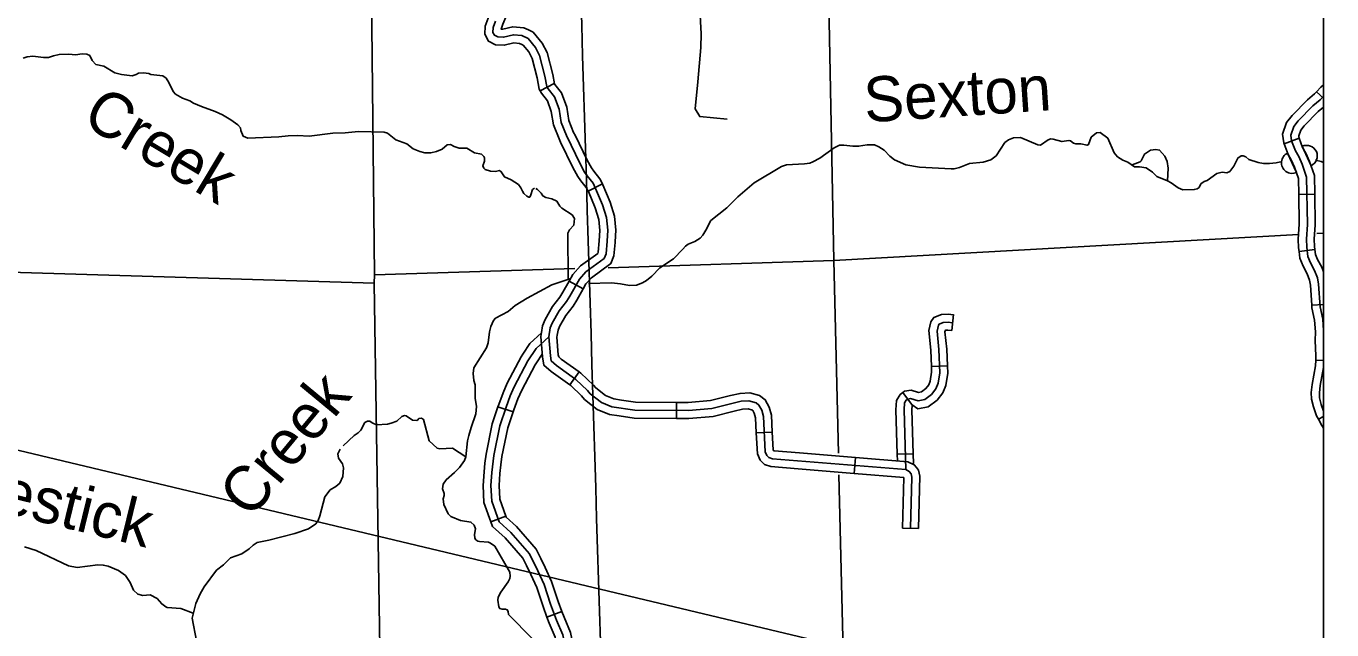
# Model space of a CAD drawing. Extents: x 1212896 to 1368412, y 378476 to 478763.
# Drawn here: x 1307154 to 1319396, y 397540 to 403202 of the extents above; entities that cross this region are included whole.
import ezdxf

# ---------------------------------------------------------------- set-up
doc = ezdxf.new("R2010")
doc.units = 0
for name, color, linetype in [('1', 7, 'Continuous'), ('Level 31', 7, 'Continuous'), ('Level 32', 7, 'Continuous'), ('Level 35', 7, 'Continuous'), ('Level 38', 7, 'Continuous'), ('Level 4', 7, 'Continuous'), ('Level 45', 7, 'Continuous'), ('Level 5', 7, 'Continuous'), ('Level 60', 7, 'Continuous'), ('R_Draft', 7, 'Continuous')]:
    doc.layers.add(name, color=color, linetype=linetype)

msp = doc.modelspace()

# ---------------------------------------------------------------- linework, layer by layer
at = {"layer": '1'}
msp.add_lwpolyline([(1257400, 437504), (1319317, 437504), (1319317, 388319), (1257400, 388319)], close=True, dxfattribs=at)
at = {"layer": 'Level 31'}
for p, q in [((1312105, 402665), (1311973, 402595)), ((1312423, 401654), (1312557, 401722)), ((1312245, 400812), (1312376, 400739)), ((1312133, 400305), (1312133, 400305)), ((1312338, 399961), (1312251, 399839)), ((1313252, 399524), (1313253, 399674)), ((1314149, 399395), (1313999, 399387)), ((1314918, 399007), (1314930, 399157)), ((1315519, 398491), (1315369, 398495))]:
    msp.add_line(p, q, dxfattribs=at)
for points in [[(1311801, 403030), (1311779, 403040), (1311727, 403046), (1311637, 403023), (1311555, 403028), (1311490, 403060), (1311455, 403126), (1311458, 403203), (1311485, 403278), (1311522, 403362)], [(1312415, 401798), (1312390, 401832), (1312347, 401911), (1312219, 402175), (1312171, 402297), (1312151, 402422), (1312107, 402540), (1312048, 402614), (1312035, 402637), (1312017, 402734), (1311968, 402927), (1311929, 403001), (1311860, 403085), (1311800, 403113), (1311722, 403121), (1311630, 403098), (1311575, 403102), (1311545, 403117), (1311531, 403143), (1311532, 403189), (1311554, 403250)], [(1311864, 403166), (1311820, 403186), (1311717, 403197), (1311622, 403174), (1311607, 403175), (1311624, 403222), (1311659, 403301)], [(1312107, 402662), (1312091, 402750), (1312038, 402954), (1311992, 403043), (1311907, 403146), (1311864, 403166)], [(1311973, 402595), (1311964, 402612), (1311944, 402718), (1311897, 402900), (1311866, 402960), (1311813, 403024), (1311801, 403030)], [(1312300, 402180), (1312287, 402205), (1312243, 402316), (1312224, 402441), (1312173, 402578), (1312110, 402656), (1312105, 402665)], [(1311973, 402595), (1311985, 402572), (1312041, 402503), (1312078, 402403), (1312098, 402277), (1312150, 402145), (1312165, 402114)], [(1312557, 401722), (1312533, 401769), (1312475, 401843), (1312454, 401872), (1312414, 401946), (1312300, 402180)], [(1312165, 402114), (1312280, 401877), (1312327, 401792), (1312356, 401752), (1312406, 401688), (1312423, 401654)], [(1312574, 401023), (1312592, 401067), (1312603, 401185), (1312608, 401288), (1312596, 401406), (1312559, 401525), (1312493, 401681), (1312469, 401729), (1312415, 401798)], [(1312528, 401188), (1312528, 401190), (1312533, 401286), (1312522, 401390), (1312488, 401499), (1312425, 401650), (1312423, 401654)], [(1312677, 401174), (1312678, 401179), (1312684, 401290), (1312669, 401421), (1312629, 401550), (1312561, 401713), (1312557, 401722)], [(1312245, 400812), (1312279, 400873), (1312353, 400955), (1312513, 401071), (1312518, 401084), (1312528, 401188)], [(1312376, 400739), (1312402, 400785), (1312454, 400843), (1312636, 400975), (1312665, 401049), (1312677, 401174)], [(1312069, 400111), (1312054, 400288), (1312068, 400372), (1312086, 400418), (1312153, 400531), (1312220, 400620), (1312252, 400670), (1312341, 400829), (1312403, 400899), (1312574, 401023)], [(1311985, 400329), (1311995, 400392), (1312019, 400451), (1312090, 400572), (1312158, 400662), (1312187, 400708), (1312245, 400812)], [(1312376, 400739), (1312316, 400632), (1312282, 400577), (1312215, 400489), (1312154, 400385), (1312141, 400352), (1312133, 400305)], [(1312251, 399839), (1312078, 399962), (1312009, 400022), (1311994, 400101), (1311979, 400291), (1311985, 400329)], [(1312133, 400305), (1312130, 400285), (1312143, 400121), (1312147, 400101), (1312171, 400079), (1312338, 399961)], [(1312441, 399755), (1312418, 399785), (1312308, 399890), (1312125, 400020), (1312078, 400062), (1312069, 400111)], [(1312737, 399696), (1312664, 399706), (1312585, 399739), (1312494, 399809), (1312473, 399835), (1312356, 399948), (1312338, 399961)], [(1312715, 399547), (1312624, 399560), (1312509, 399608), (1312388, 399702), (1312362, 399734), (1312260, 399832), (1312251, 399839)], [(1315444, 398493), (1315459, 398974), (1315452, 399004), (1315433, 399027), (1315400, 399043), (1314152, 399146), (1314117, 399158), (1314099, 399176), (1314084, 399210), (1314067, 399541), (1314051, 399600), (1314024, 399648), (1313997, 399669), (1313931, 399687), (1313858, 399684), (1313582, 399618), (1313364, 399598), (1312861, 399602), (1312644, 399633), (1312547, 399673), (1312441, 399755)], [(1313253, 399674), (1312866, 399677), (1312737, 399696)], [(1313253, 399674), (1313361, 399673), (1313569, 399692), (1313757, 399737)], [(1313757, 399737), (1313848, 399758), (1313940, 399763), (1314031, 399738), (1314083, 399698), (1314121, 399628), (1314141, 399553), (1314149, 399395)], [(1313792, 399591), (1313594, 399543), (1313367, 399523), (1313252, 399524)], [(1313999, 399387), (1313992, 399529), (1313981, 399572), (1313966, 399598), (1313963, 399601), (1313923, 399612), (1313869, 399609), (1313792, 399591)], [(1313252, 399524), (1312855, 399527), (1312715, 399547)], [(1314392, 399051), (1314136, 399072), (1314076, 399092), (1314036, 399133), (1314010, 399192), (1313999, 399387)], [(1314404, 399200), (1314167, 399220), (1314160, 399222), (1314158, 399228), (1314149, 399395)], [(1314930, 399157), (1314404, 399200)], [(1314930, 399157), (1315420, 399116), (1315481, 399087), (1315500, 399063)], [(1314918, 399007), (1314392, 399051)], [(1315384, 398969), (1314918, 399007)], [(1315369, 398495), (1315384, 398969)], [(1315500, 399063), (1315521, 399037), (1315534, 398981), (1315519, 398491)]]:
    msp.add_lwpolyline(points, dxfattribs=at)
at = {"layer": 'Level 32'}
for p, q in [((1319317, 402527), (1319252, 402587)), ((1319088, 402150), (1318948, 402098)), ((1319236, 401626), (1319086, 401624)), ((1319237, 401107), (1319088, 401088)), ((1319317, 400593), (1319207, 400586)), ((1315834, 400347), (1315849, 400497)), ((1319317, 400066), (1319244, 400069)), ((1315791, 400016), (1315641, 400010)), ((1315463, 399646), (1315372, 399766)), ((1319317, 399541), (1319270, 399515)), ((1315470, 399190), (1315320, 399187))]:
    msp.add_line(p, q, dxfattribs=at)
for points in [[(1311554, 403250), (1311532, 403189), (1311531, 403143), (1311545, 403117), (1311575, 403102), (1311630, 403098), (1311722, 403121), (1311800, 403113), (1311860, 403085), (1311929, 403001), (1311968, 402927), (1312017, 402734), (1312035, 402637), (1312048, 402614), (1312107, 402540), (1312151, 402422), (1312171, 402297), (1312219, 402175), (1312347, 401911), (1312390, 401832), (1312415, 401798)], [(1319317, 402651), (1319291, 402630), (1319252, 402587)], [(1319252, 402587), (1319232, 402566), (1319166, 402511), (1319022, 402365), (1318969, 402298), (1318933, 402188), (1318944, 402109), (1318948, 402098)], [(1319317, 402546), (1319285, 402511), (1319217, 402455), (1319079, 402315), (1319038, 402262), (1319011, 402180), (1319018, 402127), (1319054, 402032), (1319085, 401978), (1319116, 401907), (1319159, 401786), (1319167, 401342)], [(1319317, 402442), (1319267, 402400), (1319135, 402266), (1319104, 402226), (1319086, 402173), (1319090, 402145)], [(1319088, 402150), (1319121, 402063), (1319151, 402011), (1319185, 401934), (1319233, 401800), (1319236, 401626)], [(1318948, 402098), (1318985, 401999), (1319017, 401943), (1319045, 401879), (1319083, 401772), (1319086, 401624)], [(1312415, 401798), (1312469, 401729), (1312493, 401681), (1312559, 401525), (1312596, 401406), (1312608, 401288), (1312603, 401185), (1312592, 401067), (1312574, 401023)], [(1319086, 401624), (1319090, 401344), (1319080, 401205), (1319084, 401123), (1319088, 401088)], [(1319236, 401626), (1319240, 401340), (1319231, 401203), (1319233, 401135), (1319237, 401107)], [(1319167, 401342), (1319157, 401204), (1319160, 401129), (1319171, 401043), (1319195, 400982), (1319234, 400910), (1319261, 400842), (1319271, 400781), (1319285, 400571), (1319310, 400454), (1319317, 400349)], [(1319088, 401088), (1319096, 401025), (1319125, 400950), (1319164, 400878), (1319187, 400821), (1319195, 400772), (1319207, 400586)], [(1319237, 401107), (1319243, 401062), (1319261, 401013), (1319301, 400941), (1319317, 400899)], [(1312574, 401023), (1312403, 400899), (1312341, 400829), (1312252, 400670), (1312220, 400620), (1312153, 400531), (1312086, 400418), (1312068, 400372), (1312054, 400288), (1312069, 400111)], [(1319207, 400586), (1319209, 400560), (1319234, 400444), (1319242, 400336), (1319239, 400253), (1319246, 400110), (1319244, 400069)], [(1315840, 400421), (1315797, 400425), (1315752, 400423), (1315715, 400408), (1315708, 400397), (1315694, 400341), (1315711, 400169), (1315720, 399952), (1315705, 399853), (1315682, 399800), (1315643, 399749), (1315580, 399702), (1315516, 399689), (1315445, 399709), (1315419, 399705), (1315405, 399695), (1315389, 399669), (1315386, 399604), (1315400, 399043)], [(1315849, 400496), (1315799, 400502), (1315736, 400498), (1315664, 400470), (1315637, 400429), (1315617, 400347), (1315635, 400164), (1315641, 400010)], [(1315832, 400347), (1315795, 400351), (1315772, 400350), (1315768, 400335), (1315785, 400174), (1315791, 400016)], [(1319317, 400307), (1319316, 400254), (1319317, 400219)], [(1312069, 400111), (1312078, 400062), (1312125, 400020), (1312308, 399890), (1312418, 399785), (1312441, 399755)], [(1319244, 400069), (1319242, 400016), (1319211, 399843), (1319202, 399765), (1319204, 399704), (1319223, 399631), (1319252, 399548), (1319270, 399515)], [(1315641, 400010), (1315643, 399956), (1315631, 399874), (1315616, 399839), (1315589, 399804), (1315548, 399773), (1315519, 399768), (1315451, 399787), (1315388, 399778), (1315372, 399766)], [(1315791, 400016), (1315794, 399948), (1315776, 399833), (1315747, 399763), (1315695, 399696), (1315610, 399633), (1315513, 399613), (1315460, 399651)], [(1319317, 400002), (1319287, 399832), (1319279, 399762), (1319280, 399715), (1319296, 399653), (1319317, 399593)], [(1312441, 399755), (1312547, 399673), (1312644, 399633), (1312861, 399602), (1313364, 399598), (1313582, 399618), (1313858, 399684), (1313931, 399687), (1313997, 399669), (1314024, 399648), (1314051, 399600), (1314067, 399541), (1314084, 399210), (1314099, 399176), (1314117, 399158), (1314152, 399146), (1315400, 399043), (1315433, 399027), (1315452, 399004), (1315459, 398974), (1315444, 398493)], [(1315372, 399766), (1315348, 399747), (1315313, 399693), (1315309, 399605), (1315320, 399187)], [(1315463, 399646), (1315461, 399645), (1315459, 399603), (1315470, 399190)], [(1319270, 399515), (1319301, 399456), (1319317, 399433)], [(1315320, 399187), (1315322, 399126)], [(1315470, 399190), (1315472, 399101)]]:
    msp.add_lwpolyline(points, dxfattribs=at)
at = {"layer": 'Level 35'}
for points in [[(1307127, 402901), (1307163, 402913), (1307218, 402919), (1307317, 402907), (1307365, 402907), (1307411, 402925), (1307465, 402937), (1307554, 402939), (1307617, 402932), (1307680, 402941), (1307722, 402938), (1307750, 402928), (1307774, 402881), (1307807, 402842)], [(1307807, 402842), (1307884, 402827), (1307985, 402764), (1308049, 402750), (1308147, 402736), (1308185, 402748), (1308207, 402762), (1308256, 402763), (1308304, 402757), (1308322, 402749), (1308437, 402735), (1308468, 402713), (1308493, 402672), (1308532, 402588), (1308555, 402564), (1308620, 402528), (1308688, 402501), (1308723, 402481), (1308798, 402449), (1308925, 402403), (1308996, 402369), (1309072, 402322), (1309139, 402278), (1309163, 402248), (1309168, 402223), (1309189, 402170), (1309232, 402151), (1309523, 402163), (1309611, 402172), (1309698, 402175), (1309809, 402171), (1310030, 402198), (1310146, 402200), (1310270, 402213), (1310512, 402207), (1310541, 402198), (1310619, 402136), (1310724, 402097), (1310782, 402051), (1310844, 402027), (1310893, 402014), (1310949, 402014), (1311000, 402027), (1311054, 402049), (1311100, 402088), (1311132, 402092), (1311167, 402072), (1311214, 402058), (1311285, 402059), (1311359, 402015), (1311422, 402001), (1311444, 401979), (1311450, 401966), (1311450, 401936), (1311437, 401892), (1311444, 401870), (1311458, 401859), (1311508, 401841), (1311556, 401839), (1311591, 401847), (1311609, 401837), (1311638, 401790), (1311702, 401762), (1311771, 401716), (1311793, 401687), (1311809, 401656)], [(1313222, 401020), (1313312, 401110), (1313336, 401140), (1313362, 401159), (1313423, 401183), (1313472, 401213), (1313499, 401242), (1313528, 401290), (1313573, 401378), (1313723, 401498), (1313828, 401601), (1313979, 401733), (1314236, 401886), (1314282, 401901), (1314450, 401910), (1314500, 401917), (1314531, 401929), (1314596, 401965), (1314730, 402062), (1314778, 402085), (1314820, 402087), (1314903, 402075), (1314959, 402075), (1315039, 402090), (1315108, 402089), (1315149, 402071), (1315198, 402040), (1315250, 401982), (1315295, 401949), (1315402, 401900), (1315529, 401879), (1315826, 401864), (1315856, 401865), (1315905, 401877), (1315999, 401915), (1316125, 401926), (1316197, 401948), (1316247, 401985), (1316329, 402110), (1316363, 402137), (1316411, 402155), (1316476, 402157), (1316638, 402088), (1316664, 402085), (1316736, 402136), (1316762, 402144), (1316784, 402142), (1316865, 402119), (1316930, 402130), (1316946, 402127), (1316973, 402106), (1316994, 402099), (1317042, 402098), (1317101, 402085), (1317115, 402091), (1317138, 402160)], [(1317138, 402160), (1317188, 402203), (1317224, 402205), (1317295, 402151), (1317356, 402014), (1317386, 401975), (1317435, 401944), (1317483, 401926), (1317545, 401883), (1317591, 401883), (1317656, 401873), (1317714, 401832), (1317756, 401792), (1317855, 401752), (1317888, 401733), (1317955, 401685), (1317998, 401667), (1318105, 401670), (1318133, 401676), (1318151, 401689), (1318167, 401722), (1318199, 401745), (1318227, 401755), (1318318, 401821), (1318367, 401832), (1318410, 401827), (1318438, 401838), (1318476, 401889), (1318514, 401964), (1318545, 401985), (1318565, 401986), (1318590, 401976), (1318618, 401952), (1318705, 401924), (1318753, 401914), (1318811, 401913), (1318872, 401920), (1318913, 401928)], [(1317522, 401901), (1317599, 401930), (1317609, 401940), (1317639, 402002), (1317696, 402038), (1317745, 402046), (1317780, 402039), (1317829, 401984), (1317850, 401933), (1317860, 401871), (1317855, 401752)], [(1319243, 401946), (1319295, 401934), (1319317, 401924)], [(1311809, 401656), (1311820, 401633), (1311848, 401607), (1311868, 401597), (1311875, 401598), (1311887, 401619), (1311903, 401669), (1311920, 401682)], [(1311932, 401678), (1311947, 401670), (1311983, 401636), (1311999, 401610), (1312025, 401596), (1312082, 401582), (1312129, 401561), (1312158, 401514), (1312177, 401496), (1312274, 401431), (1312296, 401399), (1312288, 401336), (1312249, 401291), (1312234, 401262), (1312236, 400828)], [(1313222, 401020), (1313094, 400934), (1313021, 400857), (1312971, 400818), (1312932, 400796), (1312878, 400774), (1312812, 400770), (1312727, 400785), (1312642, 400795), (1312425, 400788)], [(1312260, 400835), (1312083, 400777), (1311850, 400650), (1311738, 400583), (1311672, 400527), (1311556, 400465), (1311537, 400441), (1311510, 400384), (1311499, 400334), (1311485, 400231), (1311470, 400185), (1311351, 399998), (1311345, 399945), (1311353, 399878), (1311363, 399837), (1311365, 399712), (1311377, 399634), (1311371, 399565), (1311325, 399438), (1311304, 399364), (1311292, 399312), (1311277, 399162), (1311264, 399129), (1311218, 399064), (1311171, 399016), (1311092, 398947), (1311063, 398908), (1311058, 398864), (1311074, 398819), (1311074, 398801), (1311065, 398769), (1311070, 398715), (1311110, 398630), (1311136, 398605), (1311227, 398565), (1311324, 398552), (1311354, 398523), (1311366, 398489), (1311358, 398434), (1311361, 398402), (1311371, 398385), (1311390, 398371), (1311405, 398368), (1311490, 398364), (1311509, 398355), (1311549, 398325), (1311688, 398081), (1311693, 398044), (1311688, 398022)], [(1310126, 399265), (1310231, 399363), (1310267, 399387), (1310291, 399413), (1310331, 399484), (1310355, 399499), (1310377, 399498), (1310397, 399483), (1310439, 399462), (1310542, 399469), (1310578, 399479), (1310629, 399499), (1310678, 399541), (1310701, 399552), (1310716, 399548), (1310777, 399506), (1310817, 399503), (1310828, 399509), (1310836, 399522), (1310862, 399527), (1310879, 399514), (1310933, 399313), (1311007, 399243), (1311034, 399237), (1311150, 399243), (1311277, 399162)], [(1308752, 397437), (1308712, 397651), (1308745, 397789), (1308786, 397879), (1308822, 397945), (1308940, 398102), (1309004, 398149), (1309071, 398215), (1309178, 398254), (1309244, 398300), (1309282, 398336), (1309319, 398361), (1309430, 398382), (1309674, 398445), (1309800, 398488), (1309871, 398536), (1309891, 398565), (1309907, 398610), (1309955, 398787), (1310006, 398855), (1310059, 398886), (1310094, 398916), (1310124, 398978), (1310130, 399060), (1310119, 399099), (1310083, 399150), (1310078, 399191), (1310099, 399236)], [(1307139, 398319), (1307247, 398285), (1307553, 398140), (1307634, 398127), (1307827, 398149), (1307877, 398148), (1307923, 398137), (1308019, 398096), (1308085, 398050), (1308131, 397986), (1308161, 397913), (1308202, 397875), (1308247, 397863), (1308317, 397868), (1308382, 397836), (1308425, 397784), (1308463, 397756), (1308477, 397751), (1308606, 397740), (1308721, 397697)], [(1311688, 398022), (1311673, 397990), (1311604, 397893), (1311580, 397846), (1311575, 397819), (1311585, 397757), (1311594, 397741), (1311617, 397734), (1311649, 397736), (1311665, 397730), (1311673, 397713), (1311676, 397686), (1311902, 397458)]]:
    msp.add_lwpolyline(points, dxfattribs=at)
at = {"layer": 'Level 38'}
for p, q in [((1319065, 401830), (1318981, 402012)), ((1319201, 401893), (1319118, 402075))]:
    msp.add_line(p, q, dxfattribs=at)
for centre, start, end in [((1319023, 401921), 114.5563, 294.5563), ((1319159, 401984), 294.5563, 114.5563)]:
    msp.add_arc(centre, 100, start, end, dxfattribs=at)
at = {"layer": 'Level 4'}
for points in [[(1310367, 405830), (1310419, 400869)], [(1310516, 393127), (1310497, 395518), (1310497, 395555), (1310418, 400791), (1310419, 400869)]]:
    msp.add_lwpolyline(points, dxfattribs=at)
at = {"layer": 'Level 45'}
for p, q in [((1311578, 399633), (1311720, 399585)), ((1311511, 398555), (1311652, 398607)), ((1312037, 397661), (1312178, 397713))]:
    msp.add_line(p, q, dxfattribs=at)
for points in [[(1313727, 402330), (1313469, 402354), (1313425, 402427), (1313453, 402681), (1313480, 403002), (1313483, 403130), (1313468, 403420), (1313458, 403807), (1313470, 403892), (1313593, 404250), (1313623, 404367), (1313643, 404499), (1313639, 404550)], [(1311812, 400126), (1311878, 400227), (1311986, 400325)], [(1312411, 397126), (1312352, 397138), (1312287, 397170), (1312237, 397252), (1312185, 397494), (1312126, 397632), (1312070, 397783), (1312010, 397966), (1311952, 398093), (1311872, 398254), (1311698, 398455), (1311590, 398553), (1311519, 398749), (1311512, 398894), (1311520, 399015), (1311539, 399177), (1311595, 399454), (1311654, 399629), (1311693, 399734), (1311731, 399820), (1311859, 400064), (1311935, 400179), (1312054, 400288)], [(1311578, 399633), (1311585, 399654), (1311625, 399762), (1311665, 399853), (1311796, 400101), (1311812, 400126)], [(1311938, 400044), (1311991, 400126)], [(1311720, 399585), (1311726, 399604), (1311764, 399706), (1311800, 399787), (1311925, 400025), (1311938, 400044)], [(1311456, 399105), (1311466, 399188), (1311524, 399473), (1311578, 399633)], [(1311605, 399088), (1311614, 399165), (1311669, 399434), (1311720, 399585)], [(1311511, 398555), (1311446, 398735), (1311438, 398895), (1311447, 399022), (1311456, 399105)], [(1311652, 398607), (1311595, 398765), (1311588, 398894), (1311596, 399008), (1311605, 399088)], [(1311979, 398210), (1311936, 398296), (1311753, 398509), (1311656, 398597), (1311652, 398607)], [(1311845, 398143), (1311810, 398213), (1311645, 398404), (1311527, 398511), (1311511, 398555)], [(1312037, 397661), (1312001, 397759), (1311942, 397939), (1311885, 398061), (1311845, 398143)], [(1312178, 397713), (1312142, 397808), (1312081, 397994), (1312020, 398126), (1311979, 398210)], [(1312212, 397152), (1312168, 397225), (1312115, 397471), (1312058, 397605), (1312037, 397661)], [(1312341, 397230), (1312309, 397281), (1312258, 397517), (1312197, 397660), (1312178, 397713)]]:
    msp.add_lwpolyline(points, dxfattribs=at)
at = {"layer": 'Level 5'}
for points in [[(1314636, 405652), (1314725, 401003)], [(1319083, 401247), (1314725, 401003)], [(1319317, 401260), (1319254, 401257)], [(1305026, 400954), (1310418, 400791)], [(1310419, 400869), (1312299, 400928)], [(1312610, 400937), (1314725, 401003)], [(1314725, 401003), (1314769, 399198)], [(1314774, 398996), (1314853, 395683), (1314976, 391200)]]:
    msp.add_lwpolyline(points, dxfattribs=at)
at = {"layer": 'Level 60'}
msp.add_spline([(1312810, 388462), (1311686, 425481), (1311316, 437640)], degree=3, dxfattribs=at)
at = {"layer": 'R_Draft'}
msp.add_line((1324691, 395024), (1283955, 404739), dxfattribs=at)

# ---------------------------------------------------------------- texts
at = {"layer": 'Level 35'}
for s, rotation, p in [('Sexton', 3.7663, (1315021, 402299)), ('Creek', 329.1486, (1307663, 402294)), ('Creek', 50.3999, (1309258, 398571)), ('Candlestick', 346.2464, (1305443, 399005))]:
    msp.add_text(s, height=422.4, rotation=rotation, dxfattribs=at).set_placement(p)

doc.saveas('drawing.dxf')
